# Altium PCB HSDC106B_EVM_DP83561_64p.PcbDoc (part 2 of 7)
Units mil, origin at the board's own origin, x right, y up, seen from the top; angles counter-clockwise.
Board outline 8750.24 x 6394.7 mil, 6 copper layers (Top Layer, GND1, SIG1, SIG2, GND2, Bottom Layer), stack 60.4 mil thick; 472 components, 324 nets, 1622 pads, 1086 vias.
Unrouted connection lines stored in the file: 1.
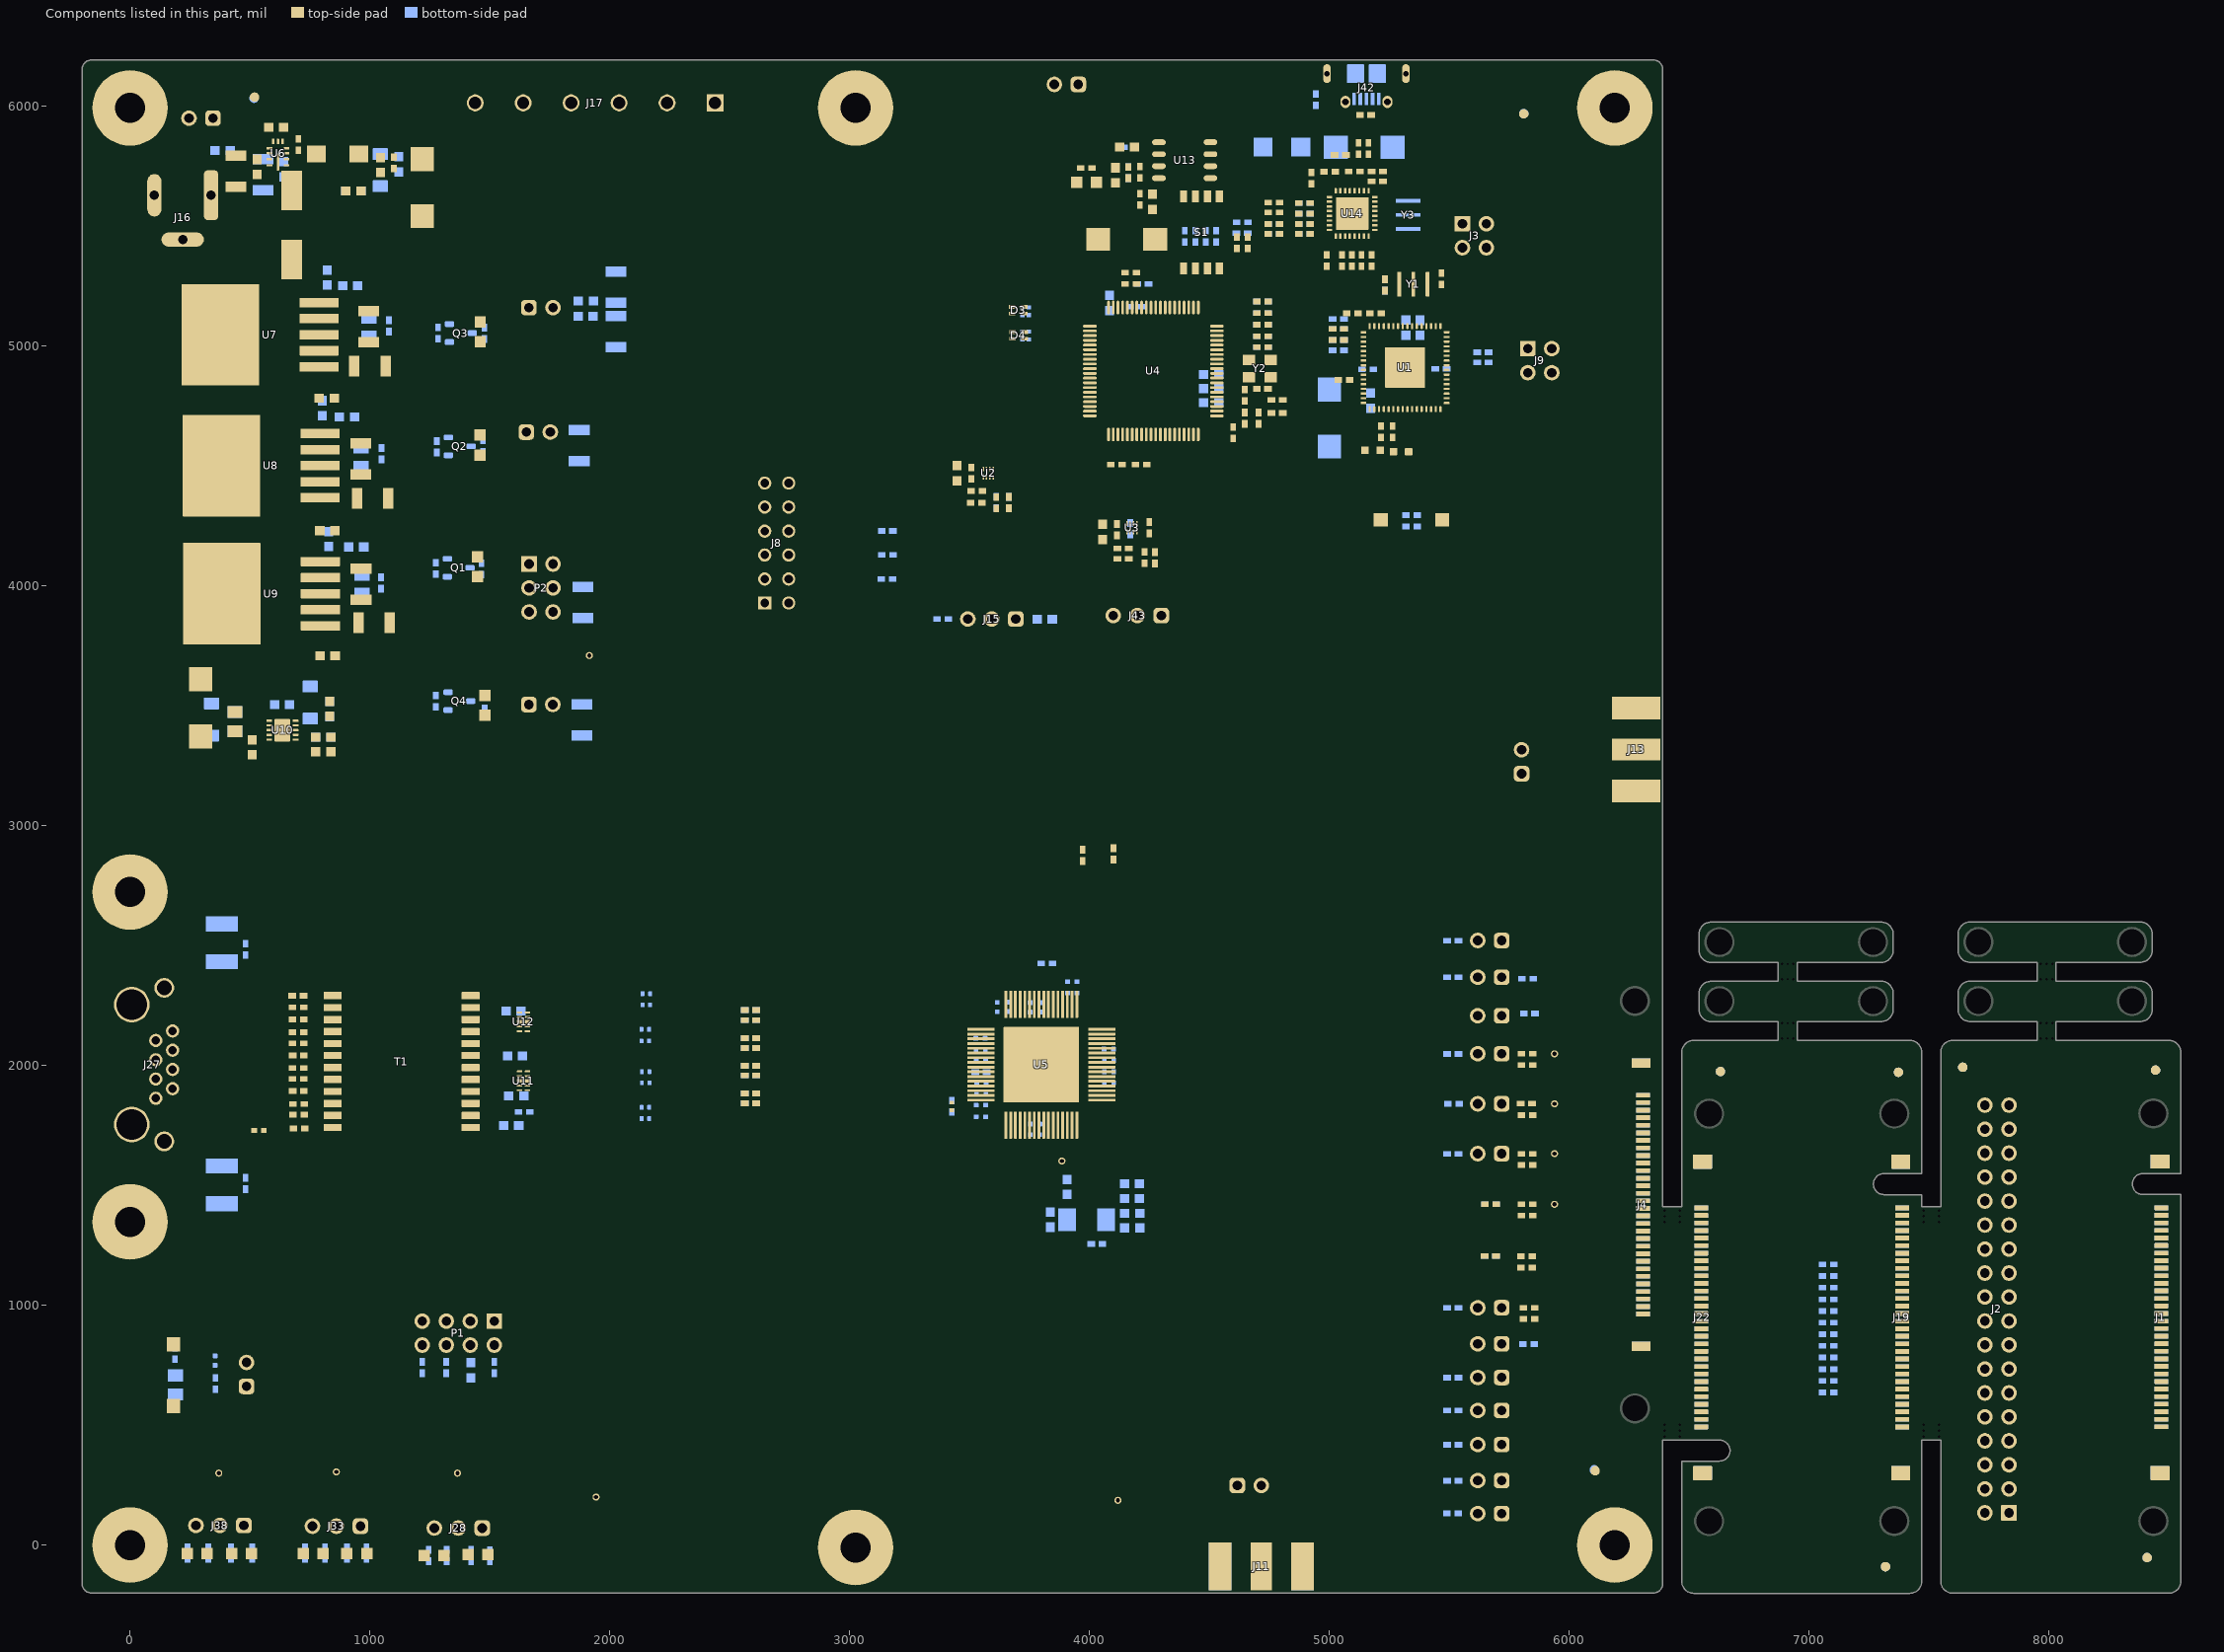
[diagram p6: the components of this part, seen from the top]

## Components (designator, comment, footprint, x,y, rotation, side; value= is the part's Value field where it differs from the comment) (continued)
R184 "CRCW040222R0JNED" 0402#1 4895.98,5596.61 r0 top value=22
R185 "CRCW040222R0JNED" 0402#1 4896.6,5552.61 r0 top value=22
R186 "CRCW040215K0FKED" 0402#1 4769,5557.5 r0 top value=15.0k
R187 "CRCW040215K0FKED" 0402#1 4769,5598.72 r0 top value=15.0k
R188 "CRCW040215K0FKED" 0402#1 5053.44,5357.32 r90 top value=15.0k
R189 "CRCW040215K0FKED" 0402#1 5094.25,5357.61 r90 top value=15.0k
R190 "CRCW040215K0FKED" 0402#1 5134.6,5357.61 r90 top value=15.0k
R191 "CRCW040215K0FKED" 0402#1 5176.79,5357.61 r90 top value=15.0k
R192 "CRCW040222R0JNED" 0402#1 4896.41,5509.5 r0 top value=22
R193 "CRCW040222R0JNED" 0402#1 4896.41,5468.5 r0 top value=22
R194 "CRCW040215K0FKED" 0402#1 4769,5468.5 r0 bottom value=15.0k
R195 "CRCW040215K0FKED" 0402#1 4769,5509.5 r0 bottom value=15.0k
R196 "CRCW040227R0JNED" 0402#1 4769,5509.5 r0 top value=27
R197 "CRCW04021K40FKED" 0402#1 4614.59,5430.77 r270 top value=1.40k
R198 "CRCW040247K0JNED" 0402#1 5045.62,5797.7 r180 top value=47k
R199 "CRCW040227R0JNED" 0402#1 4769,5468.5 r0 top value=27
R200 "CRCW04021M00FKED" 0402#1 4659.87,5430.77 r90 top value=1.00Meg
R201 "ERJ-2GE0R00X" 0402#1 7080.6,879.33 r0 bottom value=0
R202 "ERJ-2GE0R00X" 0402#1 7080.6,976.42 r0 bottom value=0
R203 "ERJ-2GE0R00X" 0402#1 7080.6,1170.61 r0 bottom value=0
R204 "ERJ-2GE0R00X" 0402#1 7080.6,1122.06 r0 bottom value=0
R205 "ERJ-2GE0R00X" 0402#1 7080.6,1073.51 r0 bottom value=0
R206 "ERJ-2GE0R00X" 0402#1 7080.6,1024.97 r0 bottom value=0
R207 "ERJ-2GE0R00X" 0402#1 7080.6,927.88 r0 bottom value=0
S1 "218-4LPST" SW_218-4LPST 4467,5474.7 r90 top
S2 "KSR221GLFS" KSR 5343,4275.7 r180 top
S3 "KSR221GLFS" KSR 181.41,708.61 r90 top
SH-J1 "M7582-05" Harwin_M7582-05 5671.6,2046 r180 top
SH-J2 "M7582-05" Harwin_M7582-05 324,69 r180 top
SH-J3 "M7582-05" Harwin_M7582-05 793.46,75 r180 top
SH-J4 "M7582-05" Harwin_M7582-05 1286.41,98 r180 top
SH-J5 "M7582-05" Harwin_M7582-05 1703,3507 r180 top
SH-J6 "M7582-05" Harwin_M7582-05 1686,4085 r180 top
SH-J7 "M7582-05" Harwin_M7582-05 1695,4636.75 r180 top
SH-J8 "M7582-05" Harwin_M7582-05 1710.75,5165.89 r180 top
T1 "1000B-5001X" FP-1000B-5001X_SMD24-MFG 1132.26,2016.7 r90 top
TP1 "TP_H0.45P0.75" TP_H045P075 1365,300 r0 top
TP2 "" TP_H045P075 370,300 r0 top
TP3 "" TP_H045P075 860,305 r0 top
TP4 "" TP_H045P075 1943,200.61 r0 top
TP5 "" TP_H045P075 1915,3710 r0 top
TP6 "" TP_H045P075 4118.6,186.61 r0 top
TP7 "" TP_H045P075 5938.99,1840.58 r0 top
TP8 "" TP_H045P075 5938.99,2048.82 r270 top locked
TP9 "" TP_H045P075 5938.99,1632.34 r270 top locked
TP10 "" TP_H045P075 5938.99,1421.22 r270 top locked
U1 "MSP430F5528IRGCR" RGC0064B 5315.99,4910.69 r0 top locked
U2 "LSF0102DQER" DQE0008A 3577.93,4470.51 r90 top
U3 "LSF0102DQER" DQE0008A 4176.6,4242.61 r90 top
U4 "MSP430F5529IPN" PN0080A_N 4266.47,4896.46 r270 top locked
U5 "DP83561HBE/EM" HBE0064B-MFG 3799.56,2003.23 r0 top locked
U6 "LMR33620ARNXT" RNX0012B 616.6,5798.61 r180 top
U7 "TL1963AQKTTRQ1" KTT0005A_N 542.35,5047.7 r180 top
U8 "TL1963AQKTTRQ1" KTT0005A_N 546.35,4501.7 r180 top
U9 "TL1963AQKTTRQ1" KTT0005A_N 547.35,3967.7 r180 top
U10 "TPS74701DRCR" DRC0010J 635,3398.7 r0 top locked
U11 "TPD4E05U06DQAR" DQA0010A 1640.56,1936.31 r0 top
U12 "TPD4E05U06DQAR" DQA0010A 1640.56,2182.31 r0 top
U13 "TL5209DR" D0008A_N 4397,5775.7 r0 top
U14 "TUSB2046BIRHBT" RHB0032E 5095.41,5553.5 r270 top
VPP_TP1 "TP_H0.45P0.75" TP_H045P075 3885,1602.05 r90 top
XTAL1 "ABM3-25.000MHZ-D2Y-T" XTAL_ABM3 3987.97,1356.8 r180 bottom
Y1 "CSTNR4M00GH5L000R0" MuRata_CSTNR 5350.6,5258.61 r0 top
Y2 "ECS-240-20-33-DU-TR" ECS_ECX-32 4710.6,4906.61 r270 top
Y3 "CSTCR6M00G53Z-R0" Murata_CSTCR_G 5329.46,5547.35 r270 bottom
ZZ1 "These assemblies are ESD sensitive, ESD precautions shall be observed." AssemblyNote 3959.7,-1368 r0 top
ZZ2 "These assemblies must be clean and free from flux and all contaminants. Use of no clean flux is not acceptable." AssemblyNote 2406.7,-1191 r0 top
ZZ3 "These assemblies must comply with workmanship standards IPC-A-610 Class 2, unless otherwise specified." AssemblyNote 2733.7,-1014 r0 top

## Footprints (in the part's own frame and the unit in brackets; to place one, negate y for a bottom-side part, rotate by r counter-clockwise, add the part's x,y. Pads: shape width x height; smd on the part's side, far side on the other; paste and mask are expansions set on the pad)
0201 [mm] "Data from Kemet datasheet CC101_COM dated 7/28/11"
  rect 0.46x0.42 smd mask+0.048: 1(-0.33,0) 2(0.33,0)
  body extent -0.31,-0.16 0.31,0.16, height 0.26
0402#1 [mm] "0402 from SM-752 data"
  rect 0.8x0.6 smd: 1(-0.6,0) 2(0.6,0)
  silkscreen extent -1.22,-0.52 1.22,0.52, body extent -0.55,-0.3 0.55,0.3, height 0.6
0402#2 [mm] "Chip Capacitor, Body 1.0x0.5mm, IPC High Density"
  rect 0.6x0.5 smd: 1(-0.5,0) 2(0.5,0)
  body extent -0.55,-0.3 0.55,0.3, height 1.3
0603 [mm] "0603 from SM-752 data"
  rect 1x0.95 smd: 1(-0.8,0) 2(0.8,0)
  silkscreen extent -1.52,-0.69 1.52,0.69, body extent -0.87,-0.47 0.87,0.47, height 1
0805_HV [mil] "0805 with 30mil clearance between pads"
  rect 50x63 smd: 1(-40,0) 2(40,0)
  silkscreen extent -74,-40 74,40, body extent -43,-29 43,29, height 57
1210_280 [mm] "SMD, 2-Leads, Body 3.6x2.8mm, Height 2.8mm"
  rect 1.1x2.2 smd: 1(-1.65,0) 2(1.65,0)
  silkscreen extent -0.84,-1.4 0.84,1.4, body extent -1.8,-1.4 1.8,1.4, height 2.8
1812_254 [mm] "SMD, 2-Leads, Body 4.8x3.4mm"
  rect 1.6x3.4 smd: 1(-2,0) 2(2,0)
  silkscreen extent -0.8,-1.7 0.8,1.7, body extent -2.4,-1.7 2.4,1.7, height 2.54
7343-31 [mm] "Medium Density based on Kemet T495 dimensions"
  rect 2.55x2.45 smd: 1(-3.025,0) 2(3.025,0)
  silkscreen extent -4.56,-2.3 3.8,2.3, body extent -3.8,-2.3 3.8,2.3, height 3.1
AssemblyNote [mil] "Assembly Note"
CAPSMT_62_HA0 [mm] "8 x 10mm:  Chemi-Con HA0"
  rect 4.2x2.2 smd: 1(-3.65,0) 2(3.65,0)
  silkscreen extent -4.25,-4.25 4.25,4.25, body extent -4.25,-4.25 4.25,4.25, height 10.5
CE_Mark_5mm [mil] "Minimum text height for CE Mark"
  silkscreen extent -138,-98 138,98
CUI_PJ-002AH [mm] "DC POWER JACK, R/A, TH"
  rrect50% 1.5x5.25 hole 1 square: 1(-3,0)
  oval 1.5x4.5 hole 1 square: 2(3,0)
  oval 4.5x1.5 hole 1 square: 3(0,4.7)
  silkscreen extent -4.1,-4.5 10.7,4.5, body extent -3.7,-4.5 10.7,4.9, height 11
D0008A_N [mm] "SOIC, 8-Leads, Body 4.9x3.9mm, Pitch 1.27mm, IPC Medium Density"
  oval 1.45x0.6 smd: 1(-2.725,1.905) 2(-2.725,0.635) 3(-2.725,-0.635) 4(-2.725,-1.905) 5(2.725,-1.905) 6(2.725,-0.635) 7(2.725,0.635) 8(2.725,1.905)
  silkscreen extent -3.3,-2.5 0.9,2.5, body extent -3,-2.45 3,2.45, height 1.63
DQA0010A [mm] "SON, 10-Leads, Body 1x2.5mm, Pitch 0.5mm, TI Recommended"
  rrect50% 0.565x0.2 smd: 1(-0.417,1) 2(-0.417,0.5) 4(-0.417,-0.5) 5(-0.417,-1) 6(0.417,-1) 7(0.417,-0.5) 9(0.417,0.5) 10(0.417,1)
  rrect28% 0.565x0.36 on Top Paste: 3(-0.417,0) 8(0.417,0)
  rrect25% 0.565x0.4 smd paste-0.2: 3(-0.417,0) 8(0.417,0)
  silkscreen extent -0.67,-1.45 0.55,1.45, body extent -0.55,-1.3 0.55,1.3, height 0.56
DQE0008A [mm] "SON, 8-Leads, Body 1.4x1mm, Pitch 0.35mm, TI Recommended"
  rect 0.6x0.16 smd: 1(-0.4,0.525)
  rect 0.5x0.16 smd: 2(-0.45,0.175) 3(-0.45,-0.175) 4(-0.45,-0.525) 5(0.45,-0.525) 6(0.45,-0.175) 7(0.45,0.175) 8(0.45,0.525)
  silkscreen extent -0.7,-0.85 0.4,0.85, body extent -0.53,-0.72 0.53,0.73, height 0.41
DRC0010J [mm] "VSON-10"
  rrect42% 0.6x0.24 smd: 1(-1.4,1) 2(-1.4,0.5) 3(-1.4,0) 4(-1.4,-0.5) 5(-1.4,-1) 6(1.4,-1) 7(1.4,-0.5) 8(1.4,0) 9(1.4,0.5) 10(1.4,1)
  rrect12% 1.65x2.4 smd paste-1 mask-2: 11(0,0)
  Top Layer region: -0.375,-1.65 -0.375,-1.2 -0.775,-1.2 -0.794,-1.196 -0.81,-1.185 -0.821,-1.169 -0.825,-1.15 -0.825,-1.15 -0.825,1.15 -0.821,1.169 -0.81,1.185 -0.794,1.196 -0.775,1.2 -0.775,1.2 -0.375,1.2 -0.375,1.65 -0.371,1.669 -0.36,1.685 -0.344,1.696 -0.325,1.7 -0.325,1.7 -0.325,1.7 -0.175,1.7 -0.175,1.7 -0.156,1.696 -0.14,1.685 -0.129,1.669 -0.125,1.65 -0.125,1.65 -0.125,1.2 0.125,1.2 0.125,1.65 0.129,1.669 0.14,1.685 0.156,1.696 0.175,1.7 0.175,1.7 0.175,1.7 0.325,1.7 0.325,1.7 0.344,1.696 0.36,1.685 0.371,1.669 0.375,1.65 0.375,1.65 0.375,1.2 0.775,1.2 0.794,1.196 0.81,1.185 0.821,1.169 0.825,1.15 0.825,1.15 0.825,-1.15 0.821,-1.169 0.81,-1.185 0.794,-1.196 0.775,-1.2 0.775,-1.2 0.375,-1.2 0.375,-1.65 0.371,-1.669 0.36,-1.685 0.344,-1.696 0.325,-1.7 0.325,-1.7 0.175,-1.7 0.156,-1.696 0.14,-1.685 0.129,-1.669 0.125,-1.65 0.125,-1.65 0.125,-1.2 -0.125,-1.2 -0.125,-1.65 -0.129,-1.669 -0.14,-1.685 -0.156,-1.696 -0.175,-1.7 -0.175,-1.7 -0.325,-1.7 -0.344,-1.696 -0.36,-1.685 -0.371,-1.669 -0.375,-1.65
  body extent -1.5,-1.5 1.5,1.5, height 1
ECS_ECX-32 [mm] "SMD, 4-Leads, Body 3.2x2.5mm"
  rect 1.1x1.3 smd: 1(-0.9,1.15) 2(-0.9,-1.15) 3(0.9,-1.15) 4(0.9,1.15)
  silkscreen extent -1.31,-0.2 1.3,2.37, body extent -1.25,-1.6 1.25,1.6, height 0.81
Emerson_142-0701-851 [mil] "Cinch Connectivity"
  rect 90x200 smd: 1(0,-110)
  rect 95x200 smd: 2(-172.5,-110) 3(172.5,-110)
  rect 95x200 smd far side: 4(172.5,-110) 5(-172.5,-110)
  silkscreen extent -235,-220 235,0, body extent -190,-195 190,387, height 155
FCC_disclaimer [mil]
Fiducial10-30 [mm]
  round 1 smd mask+1: 1(0,0)
  Top Layer keep-out circle w1.678: c0,0 r0.75
FP-1000B-5001X_SMD24-MFG [mm]
  rrect13% 0.76x1.905 smd paste+0 mask+0: 1(-6.985,-7.305) 2(-5.715,-7.305) 3(-4.445,-7.305) 4(-3.175,-7.305) 5(-1.905,-7.305) 6(-0.635,-7.305) 7(0.635,-7.305) 8(1.905,-7.305) 9(3.175,-7.305) 10(4.445,-7.305) 11(5.715,-7.305) 12(6.985,-7.305) 13(6.985,7.305) 14(5.715,7.305) 15(4.445,7.305) 16(3.175,7.305) 17(1.905,7.305) 18(0.635,7.305) 19(-0.635,7.305) 20(-1.905,7.305) 21(-3.175,7.305) 22(-4.445,7.305) 23(-5.715,7.305) 24(-6.985,7.305)
  silkscreen extent -8.89,-9.03 8.89,6.22, body extent -8.99,-8.36 8.99,8.36, height 0.25
FP-885012205067_0402-MFG [mm]
  rrect20% 0.5x0.5 smd paste+0 mask+0: 1(-0.5,0) 2(0.5,0)
  silkscreen extent -0.53,-0.63 0.53,0.63, body extent -0.5,-0.25 0.5,0.25, height 0.55
FP-CC0402KRX5R6BB104_0402-MFG [mm]
  rrect20% 0.5x0.5 smd paste+0 mask+0: 1(-0.5,0) 2(0.5,0)
  silkscreen extent -0.53,-0.71 0.53,0.7, body extent -0.5,-0.25 0.5,0.25, height 0.55
FP-CGA2B2X5R1C333K050BA_0402-MFG [mm]
  rrect25% 0.4x0.5 smd paste+0 mask+0: 1(-0.4,0) 2(0.4,0)
  silkscreen extent -0.53,-0.63 0.53,0.63, body extent -0.5,-0.25 0.5,0.25, height 0.55
FP-GCM1555C1H470FA16D_0402-MFG [mm]
  rrect25% 0.4x0.5 smd paste+0 mask+0: 1(-0.4,0) 2(0.4,0)
  silkscreen extent -0.53,-0.65 0.53,0.65, body extent -0.7,-0.38 0.7,0.38, height 0.25
FP-GMJ316BB7106MLHT_1206-MFG [mm]
  rrect8% 1.25x1.6 smd paste+0 mask+0: 1(-1.7,0) 2(1.7,0)
  silkscreen extent -0.7,-0.95 0.7,0.95, body extent -1.6,-0.8 1.6,0.8, height 1.9
Harwin_M7582-05 [mil] "Single Operation 2.54mm Pitch Open Top Jumper Socket"
  body extent -98,-47 98,47, height 236
HBE0064B-MFG [mm]
  rrect33% 2.895x0.3 smd paste+0 mask+0: 1(-6.397,3.75) 2(-6.397,3.25) 3(-6.397,2.75) 4(-6.397,2.25) 5(-6.397,1.75) 6(-6.397,1.25) 7(-6.397,0.75) 8(-6.397,0.25) 9(-6.397,-0.25) 10(-6.397,-0.75) 11(-6.397,-1.25) 12(-6.397,-1.75) 13(-6.397,-2.25) 14(-6.397,-2.75) 15(-6.397,-3.25) 16(-6.397,-3.75) 33(6.397,-3.75) 34(6.397,-3.25) 35(6.397,-2.75) 36(6.397,-2.25) 37(6.397,-1.75) 38(6.397,-1.25) 39(6.397,-0.75) 40(6.397,-0.25) 41(6.397,0.25) 42(6.397,0.75) 43(6.397,1.25) 44(6.397,1.75) 45(6.397,2.25) 46(6.397,2.75) 47(6.397,3.25) 48(6.397,3.75)
  rrect33% 0.3x2.895 smd paste+0 mask+0: 17(-3.75,-6.397) 18(-3.25,-6.397) 19(-2.75,-6.397) 20(-2.25,-6.397) 21(-1.75,-6.397) 22(-1.25,-6.397) 23(-0.75,-6.397) 24(-0.25,-6.397) 25(0.25,-6.397) 26(0.75,-6.397) 27(1.25,-6.397) 28(1.75,-6.397) 29(2.25,-6.397) 30(2.75,-6.397) 31(3.25,-6.397) 32(3.75,-6.397) 49(3.75,6.397) 50(3.25,6.397) 51(2.75,6.397) 52(2.25,6.397) 53(1.75,6.397) 54(1.25,6.397) 55(0.75,6.397) 56(0.25,6.397) 57(-0.25,6.397) 58(-0.75,6.397) 59(-1.25,6.397) 60(-1.75,6.397) 61(-2.25,6.397) 62(-2.75,6.397) 63(-3.25,6.397) 64(-3.75,6.397)
  rrect1% 8x8 smd paste-1000 mask+0: 65(0,0)
  silkscreen extent -8.54,-5.52 5.52,5.52, body extent -7.94,-7.94 7.94,7.94, height 0.25
HSMF-C165_RG [mm] "SMD, 4-Leads, Body 1.6x0.8mm"
  rect 0.7x0.4 smd: 1(-0.65,0.35) 2(-0.65,-0.35) 3(0.65,0.35) 4(0.65,-0.35)
  silkscreen extent -1,-0.8 1.5,0.8, body extent -0.85,-0.45 0.85,0.45, height 0.51
Keystone_1902C [mil] "Hex Standoff, 4-40 threaded, nylon"
  round 1 on Mech4: 0(0,0)
  body extent -145,-126 146,126, height 501
KSR [mm] "C&K Components SPST switch"
  rect 1.5x1.4 smd: 1(-3.25,0) 2(3.25,0)
  silkscreen extent -3.2,-2 3.2,2, body extent -3,-1.9 3,1.9, height 2.65
KTT0005A_N [mm] "D2-PAK, 6-Leads, Body 8.9x10.2mm, Pitch 1.7mm, Lead Span 15.2mm, IPC Medium Density"
  rrect10% 4.15x1 smd: 1(-6.25,3.4) 2(-6.25,1.7) 3(-6.25,0) 4(-6.25,-1.7) 5(-6.25,-3.4)
  rrect1% 8.2x10.75 smd: 6(4.2,0)
  silkscreen extent -6.43,-5.35 -0.3,5.35, body extent -7.63,-5.08 7.63,5.08, height 4.83
Mill-Max_802-10-012-10-001000 [mm] "Header, 2.54 mm, 6x2, TH"
  rect 1.4x1.4 hole 0.9: 1(-6.35,1.27)
  round 1.4 hole 0.9: 2(-6.35,-1.27) 3(-3.81,1.27) 4(-3.81,-1.27) 5(-1.27,1.27) 6(-1.27,-1.27) 7(1.27,1.27) 8(1.27,-1.27) 9(3.81,1.27) 10(3.81,-1.27) 11(6.35,1.27) 12(6.35,-1.27)
  silkscreen extent -7.96,-2.54 7.62,2.54, body extent -7.62,-2.54 7.62,2.54, height 8.11
Molex_0475890001 [mm] "Molex"
  rrect25% 0.4x1.35 smd: 1(-1.3,4.125) 2(-0.65,4.125) 3(0,4.125) 4(0.65,4.125) 5(1.3,4.125)
  oval 1.05x1.3 hole 0.7 slot 0.85 at 90 deg: 6(2.225,4.45) 11(-2.225,4.45)
  oval 0.8x2 hole 0.6 slot 1.3 at 90 deg: 7(4.175,1.45) 10(-4.175,1.45)
  rrect6% 1.8x2 smd: 8(1.15,1.45) 9(-1.15,1.45)
  Top Layer region: 2.6,0.45 2.6,2.45 4.175,2.45 4.175,0.45
  Top Layer region: -4.175,0.45 -4.175,2.45 -2.6,2.45 -2.6,0.45
  silkscreen extent -3.75,2.85 3.75,4.3, body extent -4.32,-1.3 4.33,4.59, height 2.81
Murata_CSTCR_G [mm] "Murata"
  rect 0.4x2.6 smd: 1(-1.5,0) 2(0,0) 3(1.5,0)
  Top Layer region: -0.4,0.8 0.4,0.8 0.4,1.3 -0.4,1.3
  Top Layer region: -0.4,-1.301 -0.4,-0.801 0.4,-0.801 0.4,-1.301
  Top Layer region: -1.9,0.8 -1.1,0.8 -1.1,1.3 -1.9,1.3
  Top Layer region: -1.9,-1.301 -1.9,-0.801 -1.1,-0.801 -1.1,-1.301
  Top Layer region: 1.1,0.8 1.9,0.8 1.9,1.3 1.1,1.3
  Top Layer region: 1.1,-1.301 1.1,-0.801 1.9,-0.801 1.9,-1.301
  body extent -2.25,-1 2.25,1, height 1.16
MuRata_CSTNR [mm] "SMD, 3-Leads, Body 4.5x2mm, Pitch 1.5mm"
  rrect25% 0.4x2.6 smd: 1(-1.5,0) 2(0,0) 3(1.5,0)
  body extent -2.3,-1.05 2.3,1.05, height 1.2
"NY PMS 440 0025 PH" [mm] "4-40 nylon screw and mounting hole"
  round 8 hole 3.2: 1(0,0)
  body extent -3.3,-3.3 3.3,3.3, height 2.69
Phoenix_1729160 [mm] "Phoenix Contact"
  rect 1.8x1.8 hole 1.3 paste+0: 1(-12.7,0)
  round 1.8 hole 1.3 paste+0: 2(-7.62,0) 3(-2.54,0) 4(2.54,0) 5(7.62,0) 6(12.7,0)
  silkscreen extent -15.81,-4.63 15.24,4.05, body extent -15.81,-4.05 15.24,4.05, height 10.01
PN0080A_N [mm] "QFP, 80-Leads, Body 12x12mm, Pitch 0.5mm, IPC Medium Density"
  oval 1.45x0.3 smd: 1(-6.725,4.75) 2(-6.725,4.25) 3(-6.725,3.75) 4(-6.725,3.25) 5(-6.725,2.75) 6(-6.725,2.25) 7(-6.725,1.75) 8(-6.725,1.25) 9(-6.725,0.75) 10(-6.725,0.25) 11(-6.725,-0.25) 12(-6.725,-0.75) 13(-6.725,-1.25) 14(-6.725,-1.75) 15(-6.725,-2.25) 16(-6.725,-2.75) 17(-6.725,-3.25) 18(-6.725,-3.75) 19(-6.725,-4.25) 20(-6.725,-4.75) 41(6.725,-4.75) 42(6.725,-4.25) 43(6.725,-3.75) 44(6.725,-3.25) 45(6.725,-2.75) 46(6.725,-2.25) 47(6.725,-1.75) 48(6.725,-1.25) 49(6.725,-0.75) 50(6.725,-0.25) 51(6.725,0.25) 52(6.725,0.75) 53(6.725,1.25) 54(6.725,1.75) 55(6.725,2.25) 56(6.725,2.75) 57(6.725,3.25) 58(6.725,3.75) 59(6.725,4.25) 60(6.725,4.75)
  oval 0.3x1.45 smd: 21(-4.75,-6.725) 22(-4.25,-6.725) 23(-3.75,-6.725) 24(-3.25,-6.725) 25(-2.75,-6.725) 26(-2.25,-6.725) 27(-1.75,-6.725) 28(-1.25,-6.725) 29(-0.75,-6.725) 30(-0.25,-6.725) 31(0.25,-6.725) 32(0.75,-6.725) 33(1.25,-6.725) 34(1.75,-6.725) 35(2.25,-6.725) 36(2.75,-6.725) 37(3.25,-6.725) 38(3.75,-6.725) 39(4.25,-6.725) 40(4.75,-6.725) 61(4.75,6.725) 62(4.25,6.725) 63(3.75,6.725) 64(3.25,6.725) 65(2.75,6.725) 66(2.25,6.725) 67(1.75,6.725) 68(1.25,6.725) 69(0.75,6.725) 70(0.25,6.725) 71(-0.25,6.725) 72(-0.75,6.725) 73(-1.25,6.725) 74(-1.75,6.725) 75(-2.25,6.725) 76(-2.75,6.725) 77(-3.25,6.725) 78(-3.75,6.725) 79(-4.25,6.725) 80(-4.75,6.725)
  silkscreen extent -6.85,-5.6 5.6,5.6, body extent -7,-7 7,7, height 1.56
QTLP630C_Green [mm] "SMT, 2-Leads, Body 2x1.25mm"
  rect 1.2x1.2 smd: 1(-1.05,0) 2(1.05,0)
  silkscreen extent -0.15,-0.8 2.15,0.8, body extent -1.1,-0.73 1.1,0.73, height 1.22
RGC0064B [mm] "VQFN-64"
  rrect42% 0.6x0.24 smd mask+0.07: 1(-4.4,3.75) 2(-4.4,3.25) 3(-4.4,2.75) 4(-4.4,2.25) 5(-4.4,1.75) 6(-4.4,1.25) 7(-4.4,0.75) 8(-4.4,0.25) 9(-4.4,-0.25) 10(-4.4,-0.75) 11(-4.4,-1.25) 12(-4.4,-1.75) 13(-4.4,-2.25) 14(-4.4,-2.75) 15(-4.4,-3.25) 16(-4.4,-3.75) 33(4.4,-3.75) 34(4.4,-3.25) 35(4.4,-2.75) 36(4.4,-2.25) 37(4.4,-1.75) 38(4.4,-1.25) 39(4.4,-0.75) 40(4.4,-0.25) 41(4.4,0.25) 42(4.4,0.75) 43(4.4,1.25) 44(4.4,1.75) 45(4.4,2.25) 46(4.4,2.75) 47(4.4,3.25) 48(4.4,3.75)
  rrect42% 0.24x0.6 smd mask+0.07: 17(-3.75,-4.4) 18(-3.25,-4.4) 19(-2.75,-4.4) 20(-2.25,-4.4) 21(-1.75,-4.4) 22(-1.25,-4.4) 23(-0.75,-4.4) 24(-0.25,-4.4) 25(0.25,-4.4) 26(0.75,-4.4) 27(1.25,-4.4) 28(1.75,-4.4) 29(2.25,-4.4) 30(2.75,-4.4) 31(3.25,-4.4) 32(3.75,-4.4) 49(3.75,4.4) 50(3.25,4.4) 51(2.75,4.4) 52(2.25,4.4) 53(1.75,4.4) 54(1.25,4.4) 55(0.75,4.4) 56(0.25,4.4) 57(-0.25,4.4) 58(-0.75,4.4) 59(-1.25,4.4) 60(-1.75,4.4) 61(-2.25,4.4) 62(-2.75,4.4) 63(-3.25,4.4) 64(-3.75,4.4)
  rrect2% 4.25x4.25 smd paste-2.112: 65(0,0)
  body extent -4.5,-4.5 4.5,4.5, height 1
RHB0032E [mm] "QFN, 32-Leads, Body 5x5mm, Pitch 0.5mm, Thermal Pad 3.45x3.45mm, TI Recommended"
  rrect40% 0.6x0.25 smd: 1(-2.4,1.75) 2(-2.4,1.25) 3(-2.4,0.75) 4(-2.4,0.25) 5(-2.4,-0.25) 6(-2.4,-0.75) 7(-2.4,-1.25) 8(-2.4,-1.75) 17(2.4,-1.75) 18(2.4,-1.25) 19(2.4,-0.75) 20(2.4,-0.25) 21(2.4,0.25) 22(2.4,0.75) 23(2.4,1.25) 24(2.4,1.75)
  rrect40% 0.25x0.6 smd: 9(-1.75,-2.4) 10(-1.25,-2.4) 11(-0.75,-2.4) 12(-0.25,-2.4) 13(0.25,-2.4) 14(0.75,-2.4) 15(1.25,-2.4) 16(1.75,-2.4) 25(1.75,2.4) 26(1.25,2.4) 27(0.75,2.4) 28(0.25,2.4) 29(-0.25,2.4) 30(-0.75,2.4) 31(-1.25,2.4) 32(-1.75,2.4)
  rrect3% 3.45x3.45 smd paste-1.725: 33(0,0)
  rrect7% 1.49x1.49 on Top Paste: ""(-0.845,0.845) ""(-0.845,-0.845) ""(0.845,0.845) ""(0.845,-0.845)
  silkscreen extent -2.72,-2.73 2.72,2.73, body extent -2.57,-2.57 2.58,2.58, height 1.01
RNX0012B [mm] "VQFN-HR-12"
  rrect40% 0.6x0.25 smd: 1(-0.9,1.125) 2(-0.9,0.475) 3(-0.9,-0.175) 4(-0.9,-0.675) 8(0.9,-0.675) 9(0.9,-0.175) 10(0.9,0.475) 11(0.9,1.125)
  rrect40% 0.25x0.6 smd: 5(-0.5,-1.4) 6(0,-1.4) 7(0.5,-1.4)
  rrect40% 0.25x1.825 smd paste-0.175: 12(0,0.788)
  body extent -1,-1.5 1,1.5, height 1
Samtec_ERF8-030-01-x-D-EM2 [mm] "Receptacle, 0.8mm, 30x2, Edge Mount"
  rrect20% 0.5x1.48 smd paste-1: 1(-11.6,-2.06) 3(-10.8,-2.06) 5(-10,-2.06) 7(-9.2,-2.06) 9(-8.4,-2.06) 11(-7.6,-2.06) 13(-6.8,-2.06) 15(-6,-2.06) 17(-5.2,-2.06) 19(-4.4,-2.06) 21(-3.6,-2.06) 23(-2.8,-2.06) 25(-2,-2.06) 27(-1.2,-2.06) 29(-0.4,-2.06) 31(0.4,-2.06) 33(1.2,-2.06) 35(2,-2.06) 37(2.8,-2.06) 39(3.6,-2.06) 41(4.4,-2.06) 43(5.2,-2.06) 45(6,-2.06) 47(6.8,-2.06) 49(7.6,-2.06) 51(8.4,-2.06) 53(9.2,-2.06) 55(10,-2.06) 57(10.8,-2.06) 59(11.6,-2.06)
  rrect20% 0.5x1.48 smd far side paste-1: 2(-11.6,-2.06) 4(-10.8,-2.06) 6(-10,-2.06) 8(-9.2,-2.06) 10(-8.4,-2.06) 12(-7.6,-2.06) 14(-6.8,-2.06) 16(-6,-2.06) 18(-5.2,-2.06) 20(-4.4,-2.06) 22(-3.6,-2.06) 24(-2.8,-2.06) 26(-2,-2.06) 28(-1.2,-2.06) 30(-0.4,-2.06) 32(0.4,-2.06) 34(1.2,-2.06) 36(2,-2.06) 38(2.8,-2.06) 40(3.6,-2.06) 42(4.4,-2.06) 44(5.2,-2.06) 46(6,-2.06) 48(6.8,-2.06) 50(7.6,-2.06) 52(8.4,-2.06) 54(9.2,-2.06) 56(10,-2.06) 58(10.8,-2.06) 60(11.6,-2.06)
  rrect7% 1.5x2 smd: MP1(-16.5,-2.2) MP3(16.5,-2.2)
  rrect7% 1.5x2 smd far side: MP2(-16.5,-2.2) MP4(16.5,-2.2)
  silkscreen extent -18.5,-5.2 18,-0.17, body extent -18,-5.2 18,7, height 2.14
Samtec_ERM8-030-01-L-D-EM2 [mm] "Receptacle, 0.8mm, 30x2, Edge mount"
  rect 1.45x0.5 smd: 1(2.075,11.6) 3(2.075,10.8) 5(2.075,10) 7(2.075,9.2) 9(2.075,8.4) 11(2.075,7.6) 13(2.075,6.8) 15(2.075,6) 17(2.075,5.2) 19(2.075,4.4) 21(2.075,3.6) 23(2.075,2.8) 25(2.075,2) 27(2.075,1.2) 29(2.075,0.4) 31(2.075,-0.4) 33(2.075,-1.2) 35(2.075,-2) 37(2.075,-2.8) 39(2.075,-3.6) 41(2.075,-4.4) 43(2.075,-5.2) 45(2.075,-6) 47(2.075,-6.8) 49(2.075,-7.6) 51(2.075,-8.4) 53(2.075,-9.2) 55(2.075,-10) 57(2.075,-10.8) 59(2.075,-11.6)
  rect 1.45x0.5 smd far side: 2(2.075,11.6) 4(2.075,10.8) 6(2.075,10) 8(2.075,9.2) 10(2.075,8.4) 12(2.075,7.6) 14(2.075,6.8) 16(2.075,6) 18(2.075,5.2) 20(2.075,4.4) 22(2.075,3.6) 24(2.075,2.8) 26(2.075,2) 28(2.075,1.2) 30(2.075,0.4) 32(2.075,-0.4) 34(2.075,-1.2) 36(2.075,-2) 38(2.075,-2.8) 40(2.075,-3.6) 42(2.075,-4.4) 44(2.075,-5.2) 46(2.075,-6) 48(2.075,-6.8) 50(2.075,-7.6) 52(2.075,-8.4) 54(2.075,-9.2) 56(2.075,-10) 58(2.075,-10.8) 60(2.075,-11.6)
  rect 2x1 smd: MP1(2.3,15) MP3(2.3,-15)
  rect 2x1 smd far side: MP2(2.3,15) MP4(2.3,-15)
  silkscreen extent 0.2,-16.5 5.2,16.5, body extent -7.75,-16.5 5.2,16.5, height 2.15
SMA [mm] "Molded Diode, 2-Leads, Body 4.3x2.6mm, IPC Medium Density, based on OnSemi component dimensions and land pattern"
  rect 2x2 smd: 1(-2,0) 2(2,0)
  silkscreen extent -3.66,-1.57 2.79,1.57, body extent -2.6,-1.3 2.6,1.3, height 2.42
SOT-23 [mm] "SOT23, 3-Leads, Body 2.9x1.3mm, Pitch 0.95mm, Lead Span 2.5mm, IPC Medium Density"
  rrect50% 1x0.6 smd: 1(-1.2,0.95) 2(-1.2,-0.95) 3(1.2,0)
  silkscreen extent -1.62,-1.5 0.7,1.5, body extent -1.16,-1.45 1.21,1.45, height 1
SRP5030T [mm] "Bourns"
  rect 2x1.8 smd: 1(-2.25,0) 2(2.25,0)
  silkscreen extent -3.1,-2.8 3.1,2.8, body extent -3,-2.7 3,2.7, height 3
SW_218-4LPST [mil] "CTS Components"
  rect 50x30 smd: 1(-150,75) 2(-150,25) 3(-150,-25) 4(-150,-75) 5(150,-75) 6(150,-25) 7(150,25) 8(150,75)
  silkscreen extent -114,-123 114,123, body extent -166,-123 166,123, height 104
TEC_1-406541-1 [mm] "TE Connectivity"
  round 1.4 hole 0.89: 1(3.56,-0.18) 2(2.54,1.6) 3(1.52,-0.18) 4(0.5,1.6) 5(-0.52,-0.18) 6(-1.54,1.6) 7(-2.56,-0.18) 8(-3.58,1.6)
  round 2.1 hole 1.57: 9(8.12,0.71) 10(-8.14,0.71)
  round 3.759 hole 3.251: 11(6.34,-2.72) 12(-6.36,-2.72)
  silkscreen extent -9.69,-8 9.69,8.06, body extent -9.33,-8 9.31,7.75, height 14.8
TI_Stacked_Overlay_Small [mil]
  silkscreen extent -418,-98 418,98
TP_H045P075 [mm] "TP_H0.45P0.75"
  round 0.75 hole 0.45: 1(0,0)
TSW-102-07-G-D [mm] "Samtec 100mil, 2x2, 230 mil above insulator"
  rrect6% 1.65x1.65 hole 1.016: 1(-1.27,-1.27)
  round 1.65 hole 1.016: 2(-1.27,1.27) 3(1.27,-1.27) 4(1.27,1.27)
  silkscreen extent -2.54,-3.5 2.54,2.54, body extent -2.54,-2.54 2.54,2.54, height 8.38
TSW-102-07-G-S [mm] "Samtec 100mil, 1x2, 230 mil above insulator"
  rrect50% 1.65x1.65 hole 1.016: 1(-1.27,0)
  round 1.65 hole 1.016: 2(1.27,0)
  silkscreen extent -3.17,-1.27 2.54,1.27, body extent -2.54,-1.27 2.54,1.27, height 8.38
TSW-103-07-G-D [mm] "Samtec 100mil, 2x3, 230 mil above insulator"
  rect 1.65x1.65 hole 1.016: 1(-2.54,-1.27)
  round 1.65 hole 1.016: 2(-2.54,1.27) 3(0,-1.27) 4(0,1.27) 5(2.54,-1.27) 6(2.54,1.27)
  silkscreen extent -4.83,-2.54 3.81,2.54, body extent -3.81,-2.54 3.81,2.54, height 8.38
TSW-103-07-G-S [mm] "Samtec 100mil, 1x3, 230 mil above insulator"
  rrect50% 1.65x1.65 hole 1.016: 1(-2.54,0)
  round 1.65 hole 1.016: 2(0,0) 3(2.54,0)
  body extent -3.81,-1.27 3.81,1.27, height 8.38
TSW-104-07-G-D [mm] "Samtec 100mil, 2x4, 230 mil above insulator"
  rrect6% 1.65x1.65 hole 1.016: 1(-3.81,-1.27)
  round 1.65 hole 1.016: 2(-3.81,1.27) 3(-1.27,-1.27) 4(-1.27,1.27) 5(1.27,-1.27) 6(1.27,1.27) 7(3.81,-1.27) 8(3.81,1.27)
  silkscreen extent -6.11,-2.54 5.08,2.54, body extent -5.08,-2.54 5.08,2.54, height 8.38
TSW-118-07-G-D [mm] "Samtec 100mil, 2x18, 230 mil above insulator"
  rrect6% 1.65x1.65 hole 1.016: 1(-21.59,-1.27)
  round 1.65 hole 1.016: 2(-21.59,1.27) 3(-19.05,-1.27) 4(-19.05,1.27) 5(-16.51,-1.27) 6(-16.51,1.27) 7(-13.97,-1.27) 8(-13.97,1.27) 9(-11.43,-1.27) 10(-11.43,1.27) 11(-8.89,-1.27) 12(-8.89,1.27) 13(-6.35,-1.27) 14(-6.35,1.27) 15(-3.81,-1.27) 16(-3.81,1.27) 17(-1.27,-1.27) 18(-1.27,1.27) 19(1.27,-1.27) 20(1.27,1.27) 21(3.81,-1.27) 22(3.81,1.27) 23(6.35,-1.27) 24(6.35,1.27) 25(8.89,-1.27) 26(8.89,1.27) 27(11.43,-1.27) 28(11.43,1.27) 29(13.97,-1.27) 30(13.97,1.27) 31(16.51,-1.27) 32(16.51,1.27) 33(19.05,-1.27) 34(19.05,1.27) 35(21.59,-1.27) 36(21.59,1.27)
  silkscreen extent -23.88,-2.54 22.86,2.54, body extent -22.86,-2.54 22.86,2.54, height 8.38
WEEE_Minimum [mil] "WEEElie bin"
  silkscreen extent -95,-172 99,104
WL-SMCD-0603 [mm] "SMD, 2-Leads, Body 1.6x0.8mm"
  rrect13% 0.8x0.75 smd: 1(-0.8,0) 2(0.8,0)
  body extent -0.8,-0.4 0.8,0.4, height 0.4
WL-SMCW_RED [mm] "WURTH"
  rect 0.8x0.8 smd: 1(-0.8,0) 2(0.8,0)
  silkscreen extent -1.9,-0.8 1.2,0.8, body extent -0.85,-0.45 0.85,0.45, height 0.8
XTAL_ABM3 [mm] "Abracon recommended land pattern 12.28.10"
  rect 1.9x2.4 smd: 1(-2.05,0) 2(2.05,0)
  silkscreen extent -2.67,-1.78 2.67,1.78, body extent -2.6,-1.7 2.6,1.7, height 1.3

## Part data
C1 C11 C12 C126 C129: library part CMP-0085850-1, "CAP, CERM, 0.1 µF, 16 V,+/- 10%, X7R, 0402", Cap_Case=0402, Manufacturer=Walsin, TempCo=X7R, Tolerance_%=10%, Value2=16V, ValueDisplayed=0.1µF
C2 C3: library part CMP-0006213-2, "CAP, CERM, 33 pF, 25 V, +/- 5%, C0G/NP0, 0402", Cap_Case=0402, Manufacturer="Wurth Elektronik", Supplier Part Number 1=710-885012005043, TempCo=C0G/NP0, Tolerance_%=5%, Value1=Unknown, Value2=25V, ValueDisplayed=33pF
C4 C5 C15 C16: library part CMP-0083839-1, "CAP, CERM, 36 pF, 50 V,+/- 5%, C0G/NP0, 0402", Cap_Case=0402, Manufacturer="Samsung Electro-Mechanics", TempCo=C0G/NP0, Tolerance_%=5%, Value2=50V, ValueDisplayed=36pF
C6 C9: library part CMP-0860899-1, "CAP, CERM, 0.22 µF, 50 V,+/- 10%, X5R, 0603", Cap_Case=0603, Manufacturer="Samsung Electro-Mechanics", TempCo=X5R, Tolerance_%=10%, Value2=50V, ValueDisplayed=0.22µF
C7: library part CMP-0007096-4, "CAP, CERM, 0.47 uF, 50 V, +/- 10%, X7R, AEC-Q200 Grade 1, 0603", Cap_Case=0603, Manufacturer=TDK, Supplier Part Number 1=810-CGA3E3X7R1H474K080AB, TempCo=X7R, Tolerance_%=10%, Value1="0.01064 ohm", Value2=50V, ValueDisplayed=0.47uF
C8 C25: library part CMP-0006412-2, "CAP, CERM, 1000 pF, 50 V, +/- 5%, C0G/NP0, 0402", Cap_Case=0402, Manufacturer=MuRata, Supplier Part Number 1=490-3244-1-ND, TempCo=C0G/NP0, Tolerance_%=5%, Value1=Unknown, Value2=50V, ValueDisplayed=1000pF
C10 C21: library part CMP-0011855-2, "CAP, TA, 10 uF, 35 V, +/- 10%, 0.125 ohm, SMD", Cap_Case=D, Manufacturer=AVX, Supplier Part Number 1=478-3337-1-ND, Tolerance_%=10%, Value1="0.125 ohm", Value2=35V, ValueDisplayed=10uF
C13 C14 C56: library part CMP-0006356-2, "CAP, CERM, 0.1 uF, 50 V, +/- 10%, X7R, AEC-Q200 Grade 1, 0402", Cap_Case=0402, Manufacturer=MuRata, Supplier Part Number 1=490-10672-1-ND, TempCo=X7R, Tolerance_%=10%, Value1=Unknown, Value2=50V, ValueDisplayed=0.1uF
C17 C20: library part CMP-0006905-4, "CAP, CERM, 0.22 uF, 16 V, +80/-20%, Y5V, 0603", Cap_Case=0603, Manufacturer=Kemet, Supplier Part Number 1=399-1102-1-ND, TempCo=Y5V, Tolerance_%=80%, Value1=Unknown, Value2=16V, ValueDisplayed=0.22uF
C18: library part CMP-0007138-4, "CAP, CERM, 0.47 uF, 16 V, +/- 10%, X7R, AEC-Q200 Grade 1, 0603", Cap_Case=0603, Manufacturer=MuRata, Supplier Part Number 1=490-4775-1-ND, TempCo=X7R, Tolerance_%=10%, Value1=Unknown, Value2=16V, ValueDisplayed=0.47uF
C19: library part CMP-0007022-5, "CAP, CERM, 4.7 uF, 35 V, +/- 10%, X5R, 0603", Cap_Case=0603, Manufacturer=TDK, Supplier Part Number 1=445-9064-1-ND, TempCo=X5R, Tolerance_%=10%, Value1="0.003728 ohm", Value2=35V, ValueDisplayed=4.7uF
C22 C23 C24 C117: library part CMP-0078241-1, "CAP, CERM, 0.1 µF, 10 V,+/- 10%, X7R, 0402", Cap_Case=0402, Manufacturer=Kemet, Supplier Part Number 1=399-3520-1-ND, TempCo=X7R, Tolerance_%=10%, Value2=10V, ValueDisplayed=0.1µF
C26 C28 C29 C30 C31 C32 C33 C34 C35 C36 C37 C38 C39 C40 C41 C42 C43 C44 C45: library part CMP-0093115-1, "0402 0.1 uF 10 V ±10 % Tolerance X5R SMT Multilayer Ceramic Capacitor", Digikey Part Number=311-1336-1-ND, Manufacturer=YAGEO, Mouser Part Number=603-CC402KRX5R6BB104, Operating Temperature Range="-55°C to +125°C", TempCo=30ppm/°C, Temperature Characteristic=X5R, Tolerance_%=10%, ValueDisplayed=100nF
C27: library part CMP-0006347-2, "CAP, CERM, 1 uF, 16 V, +/- 10%, X5R, 0402", Cap_Case=0402, Manufacturer="Taiyo Yuden", Supplier Part Number 1=587-3709-2-ND, TempCo=X5R, Tolerance_%=10%, Value1=Unknown, Value2=16V, ValueDisplayed=1uF
C46: library part CMP-0090364-1, "10000pF ±10% 50V Ceramic Capacitor X7R 0402 (1005 Metric)", Digikey Part Number=732-7562-1-ND, Manufacturer="Wurth Electronics", Mouser Part Number=710-885012205067, Operating Temperature Range="-55°C to +125°C", TempCo=15%, Temperature Characteristic=X7R, Tolerance_%=10%, ValueDisplayed=10000pF
C47: library part CMP-0079541-1, "CAP, CERM, 47 µF, 4 V,+/- 20%, X6S, 0805", Cap_Case=0805, Manufacturer=MuRata, Supplier Part Number 1=490-9954-1-ND, TempCo=X6S, Tolerance_%=20%, Value2=4V, ValueDisplayed=47µF
C48 C49 C94: "CAP, CERM, 27 pF, 50 V, +/- 1%, C0G/NP0, 0603", Cap_Case=0603, Manufacturer="Samsung Electro-Mechanics", PartNumber=CL10C270FB8NNNC, TempCo=C0G/NP0, Tolerance_%=1%, Value1=Unknown, Value2=50V, ValueDisplayed=27pF
C50 C52 C68 C70 C78 C80: "CAP, CERM, 10 uF, 25 V, +/- 20%, X7R, AEC-Q200 Grade 1, 1210", Cap_Case=1210, Manufacturer=TDK, PartNumber=CGA6P1X7R1E106M250AC, Supplier Part Number 1=445-5720-1-ND, TempCo=X7R, Tolerance_%=20%, Value1=Unknown, Value2=25V, ValueDisplayed=10uF
C51: library part CMP-0091135-2, "Ceramic Capacitor for Automotive 47pF ±1% 50VDC C0G 0402 Paper T/R", Manufacturer=Murata, Operating Temperature Range="-55°C to +125°C", TempCo=30ppm/°C, Temperature Characteristic=C0G, Tolerance_%=1%, ValueDisplayed=47pF
C53 C71 C81: library part CMP-0007676-2, "CAP, CERM, 1 uF, 16 V, +/- 10%, X5R, 0805", Cap_Case=0805, Manufacturer=AVX, Supplier Part Number 1=478-1411-1-ND, TempCo=X5R, Tolerance_%=10%, Value1="0.012 ohm", Value2=16V, ValueDisplayed=1uF
C54 C58 C61 C69 C72 C79 C88: "CAP, CERM, 0.01 uF, 50 V, +/- 5%, X7R, 0603", Cap_Case=0603, Manufacturer=Kemet, PartNumber=C0603C103J5RACTU, Supplier Part Number 1=399-1092-1-ND, TempCo=X7R, Tolerance_%=5%, Value1=Unknown, Value2=50V, ValueDisplayed=0.01uF
C55 C73 C83: "CAP, CERM, 0.01 uF, 50 V, +/- 10%, X7R, AEC-Q200 Grade 1, 0402", Cap_Case=0402, Manufacturer=TDK, PartNumber=CGA2B3X7R1H103K050BB, Supplier Part Number 1=445-6893-1-ND, TempCo=X7R, Tolerance_%=10%, Value1="0.333065 ohm", Value2=50V, ValueDisplayed=0.01uF
C57: library part CMP-0011752-2, "CAP, TA, 220 µF, 6.3 V, +/- 10%, 0.7 ohm, SMD", Cap_Case=D, Manufacturer=Kemet, Supplier Part Number 1=399-8378-1-ND, Tolerance_%=10, Value1="0.7 ohm", Value2=6.3V, ValueDisplayed=220µF
C59: "CAP, CERM, 100 pF, 50 V, +/- 5%, C0G/NP0, 0402", Cap_Case=0402, Manufacturer="Yageo America", PartNumber=CC0402JRNPO9BN101, Supplier Part Number 1=311-1024-1-ND, TempCo=C0G/NP0, Tolerance_%=5%, Value1=Unknown, Value2=50V, ValueDisplayed=100pF
C60 C85 C86: library part CMP-0093118-1, "Cap Ceramic 10uF 35V X7R 20% Pad SMD 1206 Soft Termination 125C Low ESR Automotive T/R", Digikey Part Number=587-4888-1-ND, Manufacturer="Taiyo Yuden", Mouser Part Number=963-GMJ316BB7106MLHT, Operating Temperature Range="-55°C to +125°C", TempCo=15%, Temperature Characteristic=X7R, Tolerance_%=20%, ValueDisplayed=10uF
C62: library part CMP-0007067-4, "CAP, CERM, 1 uF, 35 V, +/- 10%, X7R, AEC-Q200 Grade 1, 0603", Cap_Case=0603, Manufacturer=TDK, Supplier Part Number 1=445-174215-1-ND, TempCo=X7R, Tolerance_%=10%, Value1="0.005522 ohm", Value2=35V, ValueDisplayed=1uF
C63: library part CMP-0011279-3, "CAP, AL, 100 uF, 50 V, +/- 20%, SMD", Cap_Case=HA0, Manufacturer=Chemi-Con, Supplier Part Number 1=565-2252-1-ND, Tolerance_%=20%, Value1=Unknown, Value2=50V, ValueDisplayed=100uF
C64 C66: library part CMP-0009162-2, "CAP, CERM, 4.7 uF, 50 V, +/- 10%, X7R, AEC-Q200 Grade 1, 1210", Cap_Case=1210_280, Manufacturer=TDK, Supplier Part Number 1=445-6999-1-ND, TempCo=X7R, Tolerance_%=10%, Value1="0.003166 ohm", Value2=50V, ValueDisplayed=4.7uF
C65 C67: library part CMP-0007094-5, "CAP, CERM, 0.22 uF, 50 V, +/- 10%, X7R, AEC-Q200 Grade 1, 0603", Cap_Case=0603, Manufacturer=TDK, Supplier Part Number 1=445-6926-1-ND, TempCo=X7R, Tolerance_%=10%, Value1="0.021699 ohm", Value2=50V, ValueDisplayed=0.22uF
C74 C75 C76 C77 C84: "CAP, CERM, 22 uF, 16 V, +/- 20%, X7R, AEC-Q200 Grade 1, 1210", Cap_Case=1210_280, Manufacturer=TDK, PartNumber=CGA6P1X7R1C226M250AC, Supplier Part Number 1=445-5723-1-ND, TempCo=X7R, Tolerance_%=20%, Value1="0.002582 ohm", Value2=16V, ValueDisplayed=22uF
C82: library part CMP-0006236-2, "CAP, CERM, 0.01 µF, 50 V, +/- 5%, X7R, 0402", Cap_Case=0402, Manufacturer=Kemet, Supplier Part Number 1=399-7758-1-ND, TempCo=X7R, Tolerance_%=5, Value1=Unknown, Value2=50V, ValueDisplayed=0.01µF
C87: library part CMP-0007110-5, "CAP, CERM, 0.1 uF, 16 V, +/- 10%, X7R, 0603", Cap_Case=0603, Manufacturer="Samsung Electro-Mechanics", TempCo=X7R, Tolerance_%=10%, Value1=Unknown, Value2=16V, ValueDisplayed=0.1uF
C91: "CAP, TA, 100 uF, 10 V, +/- 20%, 0.1 ohm, SMD", Cap_Case=D, Manufacturer=Vishay-Sprague, PartNumber=593D107X0010D2TE3, Supplier Part Number 1=718-1100-1-ND, Tolerance_%=20%, Value1="0.1 ohm", Value2=10V, ValueDisplayed=100uF
C92: library part CMP-0007676-2, "CAP, CERM, 1 µF, 16 V, +/- 10%, X5R, 0805", Cap_Case=0805, Manufacturer=AVX, Supplier Part Number 1=478-1411-1-ND, TempCo=X5R, Tolerance_%=10, Value1="0.012 ohm", Value2=16V, ValueDisplayed=1µF
C93: library part CMP-0007960-1, "CAP, CERM, 4.7 µF, 10 V, +80/-20%, Y5V, 0805", Cap_Case=0805, Manufacturer="Yageo America", Supplier Part Number 1=311-1371-2-ND, TempCo=Y5V, Tolerance_%=80, Value1=Unknown, Value2=10V, ValueDisplayed=4.7µF
C95 C97 C99 C101 C103 C104 C106 C107: library part CMP-0091134-2, "Cap Ceramic 33nF 16V X5R 10% Pad SMD 0402 +85°C Automotive T/R", Manufacturer="TDK Corporation", Operating Temperature Range="-55°C to +85°C", TempCo=15%, Temperature Characteristic=X5R, Tolerance_%=10%, ValueDisplayed=33nF
C108 C109: "CAP, CERM, 4700 pF, 2000 V, +/- 10%, X7R, 1812", Cap_Case=1812, Manufacturer=AVX, PartNumber=1812GC472KAT1A, Supplier Part Number 1=478-3003-1-ND, TempCo=X7R, Tolerance_%=10%, Value1=Unknown, Value2=2000V, ValueDisplayed=4700pF
C110: library part CMP-0006620-2, "CAP, CERM, 1 uF, 35 V, +/- 20%, X5R, 0402", Cap_Case=0402, Manufacturer=MuRata, Supplier Part Number 1=490-10020-1-ND, TempCo=X5R, Tolerance_%=20%, Value1=Unknown, Value2=35V, ValueDisplayed=1uF
C111 C114: library part CMP-0007355-6, "CAP, CERM, 10 uF, 35 V, +/- 20%, X5R, 0603", Cap_Case=0603, Manufacturer=Murata, TempCo=X5R, Tolerance_%=20%, Value1=Unknown, Value2=35V, ValueDisplayed=10uF
C112 C113: library part CMP-0006526-2, "CAP, CERM, 2.2 uF, 16 V, +/- 10%, X6S, 0402", Cap_Case=0402, Manufacturer=MuRata, Supplier Part Number 1=GRM155C81C225KE11D-ND, TempCo=X6S, Tolerance_%=10%, Value1=Unknown, Value2=16V, ValueDisplayed=2.2uF
C115: library part CMP-0006743-4, "CAP, CERM, 470 pF, 100 V, +/- 5%, X7R, 0603", Cap_Case=0603, Manufacturer=AVX, Supplier Part Number 1=478-3709-1-ND, TempCo=X7R, Tolerance_%=5%, Value1="0.397 ohm", Value2=100V, ValueDisplayed=470pF
C116: library part CMP-0011708-2, "CAP, TA, 4.7 uF, 35 V, +/- 10%, 1.3 ohm, SMD", Cap_Case=D, Manufacturer=Vishay-Sprague, Supplier Part Number 1=718-1084-1-ND, Tolerance_%=10%, Value1="1.3 ohm", Value2=35V, ValueDisplayed=4.7uF
C118 C119 C120 C121 C124 C125: library part CMP-0860896-1, "CAP, CERM, 22 pF, 50 V,+/- 5%, C0G/NP0, 0402", Cap_Case=0402, Manufacturer=TDK, TempCo=C0G/NP0, Tolerance_%=5%, Value2=50V, ValueDisplayed=22pF
C122 C123 C127 C128: library part CMP-0079539-1, "CAP, CERM, 10 pF, 16 V,+/- 10%, C0G, 0402", Cap_Case=0402, Manufacturer=Kemet, Supplier Part Number 1=399-11110-1-ND, TempCo=C0G, Tolerance_%=10%, Value2=16V, ValueDisplayed=10pF
D1: library part CMP-0002947-3, "LED, Red, SMD", Color=Red, Manufacturer="Wurth Elektronik", Power_TotalModule=72mW, Value1=0.072W, Value2=2V
D2: library part CMP-0081648-2, "LED, Green, SMD", Color=Green, Manufacturer="Wurth Elektronik", Power_TotalModule=48mW, Value1=0.048W, Value2=2V
D3 D4: library part CMP-0002934-2, "LED, Rg, SMD", Color=RG, Manufacturer=Avago, Supplier Part Number 1=516-1419-1-ND, Value1=W, Value2=2.2V
D5 D6 D7 D8 LD1 LD2 LD3 LD4 LD5 LD6: "LED, Green, SMD", Color=Green, Manufacturer=Everlight, PartNumber=QTLP630C4TR, Value1=W, Value2=2.1V
D9: library part CMP-0028810-2, "Diode, Schottky, 60 V, 3 A, AEC-Q101, SMA", Manufacturer="Fairchild Semiconductor", Value1=3A, Value2=0.75V
F1: library part CMP-0003588-3, "Fuse, 3 A, 32 VDC, SMD", Irating_A=3A, Manufacturer=AVX, Supplier Part Number 1=478-2868-1-ND
FID1 FID2 FID3 FID4 FID5 FID6 FID7 FID8 FID9 FID10 FID11 FID12 FID13 FID14 FID15 FID16 FID17 FID18: "Fiducial mark.  There is nothing to buy or mount.", Manufacturer=N/A
H1 H2 H3 H4 H5 H6 H7 H8: library part CMP-0003610-1, "Standoff, Hex, 0.5\"L #4-40 Nylon", Manufacturer=Keystone, Supplier Part Number 1=36-1902C-ND
J1 J19 J22: library part CMP-0055720-1, "Receptacle, 0.8mm, 30x2, Gold, Edge Mount", Current_A=2.2A, Manufacturer=Samtec, Supplier Part Number 1=ERF8-030-01-L-D-EM2-TR-ND, Voltage_V=200V
J2: library part CMP-0075431-1, "Header, 100mil, 18x2, Gold, TH", Color=Black, Current_A=6.3A, Manufacturer=Samtec, Supplier Part Number 1=SAM1028-18-ND, Voltage_V=550V
J3 J9: library part CMP-0075404-1, "Header, 100mil, 2x2, Gold, TH", Color=Black, Current_A=6.3A, Manufacturer=Samtec, Supplier Part Number 1=SAM1028-02-ND, Voltage_V=550V
J4: library part CMP-0055619-1, "Receptacle, 0.8mm, 30x2, Tin, Edge mount", Color=Black, Current_A=2.2A, Manufacturer=Samtec, Supplier Part Number 1=33R2583, Voltage_V=200V
J5 J6 J10 J12 J14 J18 J20 J21 J23 J24 J29 J30 J31 J32 J34 J35 J36 J37 J39 J40 J41: library part CMP-0075405-3, "Header, 100mil, 2x1, Gold, TH", Color=Black, Current_A=6.3A, Manufacturer=Samtec, Supplier Part Number 1=SAM1029-02-ND, Voltage_V=550V
J8: library part CMP-0055098-2, "Header, 2.54 mm, 6x2, Gold, TH", Color=Black, Manufacturer=Mill-Max, Supplier Part Number 1=ED1309-12-ND
J11 J13: library part CMP-0055822-3, "Connector, End launch SMA, 50 ohm, SMT", Manufacturer="Cinch Connectivity", Supplier Part Number 1=J658-ND
J15 J28 J33 J38 J43: "Header, 100mil, 3x1, Gold, TH", Color=Black, Current_A=6.3A, Manufacturer=Samtec, PartNumber=TSW-103-07-G-S, Supplier Part Number 1=SAM1029-03-ND, Voltage_V=550V
J16: library part CMP-0078270-1, "DC POWER JACK, R/A, TH", Color=Black, Current_A=5A, Manufacturer="CUI Inc.", Supplier Part Number 1=CP-002AH-ND, Voltage_V=24V
J17: library part CMP-0055492-1, "Terminal Block, 6x1, 5.08mm, Th", Manufacturer="Phoenix Contact", Supplier Part Number 1=277-1251-ND
J27: library part CMP-0054918-1, "RJ-45, Right Angle, No LED, tab up", Manufacturer=AMP, Supplier Part Number 1=A97716-ND
J42: library part CMP-0055301-1, "Connector, Receptacle, Micro-USB Type AB, R/A, Bottom Mount SMT", Manufacturer=Molex, Supplier Part Number 1=WM17143CT-ND
L1: library part CMP-0056947-1, "Inductor, Shielded, Ferrite, 10 uH, 2.75 A, 0.128 ohm, SMD", Manufacturer=Bourns, Supplier Part Number 1=652-SRP5030T-100M, Value1="0.128 ohm", Value2=2.75A, ValueDisplayed=10uH
LD7: library part CMP-0002917-2, "LED, Green, SMD", Color=Green, Manufacturer=Everlight, Value1=W, Value2=2.1V
Logo1: library part CMP-0074844-1
Logo2: library part CMP-0074838-1, "Texas Instrument Corporate Signature"
Logo3: library part CMP-0074847-1, "FCC_disclaimer"
Logo4: library part CMP-0074769-1
M1 M2 M3 M4 M5 M6 M7 M8: library part CMP-0003617-1, "Machine Screw, Round, #4-40 x 1/4, Nylon, Philips panhead", Manufacturer="B&F Fastener Supply", Supplier Part Number 1=H542-ND
P1: "Header, 100mil, 4x2, Gold, TH", Color=Black, Current_A=6.3A, Manufacturer=Samtec, PartNumber=TSW-104-07-G-D, Supplier Part Number 1=SAM1028-04-ND, Voltage_V=550V
P2: library part CMP-0075406-2, "Header, 100mil, 3x2, Gold, TH", Color=Black, Current_A=6.3A, Manufacturer=Samtec, Supplier Part Number 1=SAM1028-03-ND, Voltage_V=550V
Q1 Q2 Q3 Q4: library part CMP-0064871-1, "Transistor, NPN, 60 V, 1 A, AEC-Q101, SOT-23", Manufacturer="Diodes Inc.", Supplier Part Number 1=DNBT8105DICT-ND, Value1="1 A", Value2=300
R1 R2 R79 R147 R149 R157 R161 R166 R170 R175: library part CMP-0026934-3, "RES, 470, 5%, 0.063 W, AEC-Q200 Grade 0, 0402", Manufacturer=Vishay-Dale, Power_W=63mW, Supplier Part Number 1=541-470JCT-ND, TempCo="200 ppm/C", Tolerance_%=5%, Value2=0.063W, Value_Code=470R, ValueDisplayed=470
R3: library part CMP-0026881-2, "RES, 240 k, 5%, 0.063 W, AEC-Q200 Grade 0, 0402", Manufacturer=Vishay-Dale, Power_W=63mW, Supplier Part Number 1=541-240KJCT-ND, TempCo="200 ppm/C", Tolerance_%=5%, Value2=0.063W, Value_Code=240k
R4 R6: library part CMP-0026877-2, "RES, 220 k, 5%, 0.063 W, AEC-Q200 Grade 0, 0402", Manufacturer=Vishay-Dale, Power_W=63mW, Supplier Part Number 1=541-220KJCT-ND, TempCo="200 ppm/C", Tolerance_%=5%, Value2=0.063W, Value_Code=220k
R5: library part CMP-0026840-2, "RES, 150 k, 5%, 0.063 W, AEC-Q200 Grade 0, 0402", Manufacturer=Vishay-Dale, Power_W=63mW, Supplier Part Number 1=541-150KJCT-ND, TempCo="200 ppm/C", Tolerance_%=5%, Value2=0.063W, Value_Code=150k
R7 R9 R10: library part CMP-0027004-2, "RES, 0, 5%, 0.063 W, 0402", Manufacturer="Yageo America", Power_W=63mW, Supplier Part Number 1=311-0.0JRCT-ND, TempCo="200 ppm/C", Tolerance_%=5%, Value2=0.063W, Value_Code=0000, ValueDisplayed=0
R8 R75 R198: library part CMP-0026935-3, "RES, 47 k, 5%, 0.063 W, AEC-Q200 Grade 0, 0402", Manufacturer=Vishay-Dale, Power_W=63mW, Supplier Part Number 1=541-47KJCT-ND, TempCo="200 ppm/C", Tolerance_%=5%, Value2=0.063W, Value_Code=47k0, ValueDisplayed=47k
R11 R12 R13 R14 R15 R16 R17 R18 R19 R20 R23 R25 R27 R29 R31 R32 R33 R34 R54 R55 R56 R57 R58 R112 R113 R115 R116 R118 R119 R120 R121 R122 R124 R125 R126 R127 R128 R129 R130 R131 R132 R133 R134 R135 R136 R137 R138 R139 R140 R141 R142 R143 R144 R201 R202 R203 R204 R205 R206 R207: library part CMP-0026992-3, "RES, 0, 5%, 0.1 W, AEC-Q200 Grade 0, 0402", Manufacturer=Panasonic, Power_W=100mW, Supplier Part Number 1=P0.0JCT-ND, TempCo="600 ppm/C", Tolerance_%=5%, Value2=0.1W, Value_Code=0000, ValueDisplayed=0
R21 R22 R24 R26 R77 R78 R82 R84 R97 R99: "RES, 0, 5%, 0.1 W, 0603", Manufacturer=Yageo, PartNumber=RC0603JR-070RL, Power_W=100mW, Supplier Part Number 1=311-0.0GRCT-ND, TempCo="200 ppm/C", Tolerance_%=5%, Value2=0.1W, Value_Code=0000, ValueDisplayed=0
R28: library part CMP-0022891-5, "RES, 1.87 k, 1%, 0.1 W, 0603", Manufacturer=Yageo, Power_W=100mW, Supplier Part Number 1=311-1.87KHRCT-ND, TempCo="100 ppm/C", Tolerance_%=1%, Value2=0.1W, Value_Code=1k87, ValueDisplayed=1.87k
R30: library part CMP-0082533-1, "RES, 4.99 k, 1%, 0.1 W, 0603", Manufacturer=Vishay-Dale, Power_W=100mW, Supplier Part Number 1=541-3985-1-ND, TempCo="100 ppm/C", Tolerance_%=1%, Value2=0.1W, Value_Code=4k99, ValueDisplayed=4.99k
R35 R37: library part CMP-0026317-2, "RES, 374 k, 1%, 0.063 W, AEC-Q200 Grade 0, 0402", Manufacturer=Vishay-Dale, Power_W=63mW, Supplier Part Number 1=541-374KLCT-ND, TempCo="100 ppm/C", Tolerance_%=1%, Value2=0.063W, Value_Code=374k
R36 R38: library part CMP-0026660-1, "RES, 1.00 M, 1%, 0.1 W, 0402", Manufacturer=Panasonic, Power_W=100mW, Supplier Part Number 1=P1.00MLCT-ND, TempCo="100 ppm/C", Tolerance_%=1%, Value2=0.1W, Value_Code=1M00, ValueDisplayed=1.00M
R40 R41: library part CMP-0025750-4, "RES, 200 k, 5%, 0.1 W, AEC-Q200 Grade 0, 0603", Manufacturer=Vishay-Dale, Power_W=100mW, Supplier Part Number 1=541-200KGCT-ND, TempCo="200 ppm/C", Tolerance_%=5%, Value2=0.1W, Value_Code=200k
R42 R43 R44: library part CMP-0026681-1, "RES, 2.20 k, 1%, 0.1 W, 0402", Manufacturer=Panasonic, Power_W=100mW, Supplier Part Number 1=P2.20KLCT-ND, TempCo="100 ppm/C", Tolerance_%=1%, Value2=0.1W, Value_Code=2k20, ValueDisplayed=2.20k
R47 R48 R51 R62 R63 R64 R65 R66 R67: library part CMP-0026231-2, "RES, 2.20 k, 1%, 0.063 W, AEC-Q200 Grade 0, 0402", Manufacturer=Vishay-Dale, Power_W=63mW, Supplier Part Number 1=541-2.20KLCT-ND, TempCo="100 ppm/C", Tolerance_%=1%, Value2=0.063W, Value_Code=2k20, ValueDisplayed=2.20k
R49 R50 R52 R53 R59 R60 R61 R179: library part CMP-0026825-5, "RES, 10 k, 5%, 0.063 W, AEC-Q200 Grade 0, 0402", Manufacturer=Vishay-Dale, Power_W=63mW, Supplier Part Number 1=541-10KJCT-ND, TempCo="200 ppm/C", Tolerance_%=5%, Value2=0.063W, Value_Code=10k0, ValueDisplayed=10k
R68 R76: library part CMP-0026822-3, "RES, 0, 5%, 0.063 W, AEC-Q200 Grade 0, 0402", Manufacturer=Vishay-Dale, Power_W=63mW, Supplier Part Number 1=541-0.0JCT-ND, TempCo="200 ppm/C", Tolerance_%=5%, Value2=0.063W, Value_Code=0000, ValueDisplayed=0
R69 R70 R71 R72: library part CMP-0027127-1, "RES, 470, 5%, 0.05 W, 0201", Manufacturer="Yageo America", Power_W=50mW, Supplier Part Number 1=311-470NCT-ND, TempCo="200 ppm/C", Tolerance_%=5%, Value2=0.05W, Value_Code=470R, ValueDisplayed=470
R73 R197: library part CMP-0026085-3, "RES, 1.40 k, 1%, 0.063 W, AEC-Q200 Grade 0, 0402", Manufacturer=Vishay-Dale, Power_W=63mW, Supplier Part Number 1=541-1.40KLCT-ND, TempCo="100 ppm/C", Tolerance_%=1%, Value2=0.063W, Value_Code=1k40, ValueDisplayed=1.40k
